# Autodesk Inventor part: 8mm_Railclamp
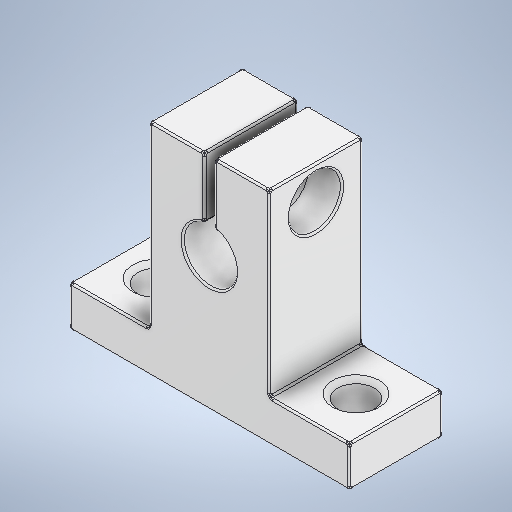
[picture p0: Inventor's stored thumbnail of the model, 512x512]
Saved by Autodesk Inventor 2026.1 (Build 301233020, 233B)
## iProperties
Created: 2026-11
Part Number: 8mm_Railclamp
Material: Steel
Document SubType Name: Modeling
Designer: hp
Density: 7.85 g/cm^3
Appearance: Default
Author: hp
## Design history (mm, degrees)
feature "Body1"
body "Solid1"
